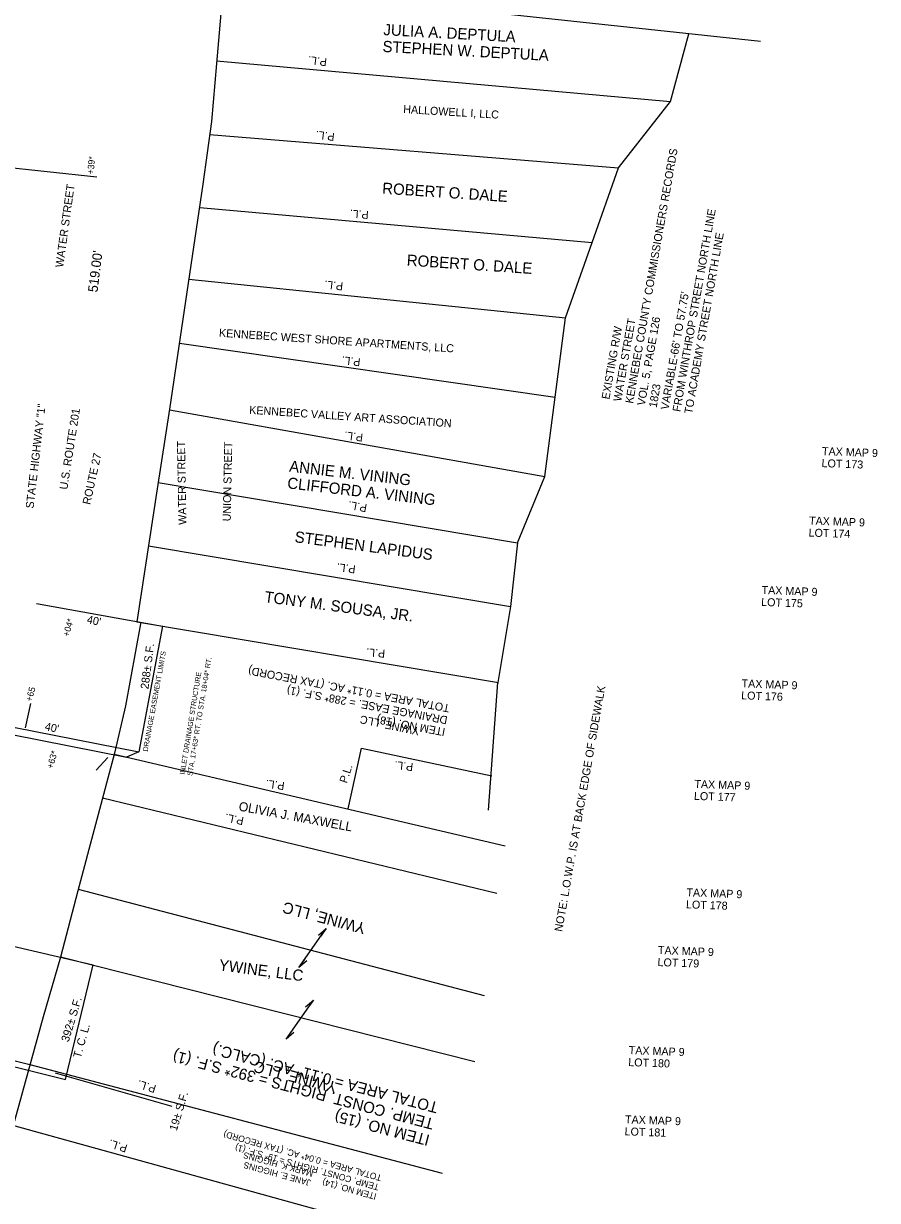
# Model space of a CAD drawing. Extents: x 1133267 to 1139526, y 528613 to 531538.
# Drawn here: x 1137374.5 to 1137641.4, y 529576.6 to 529944.3 of the extents above; entities that cross this region are included whole.
import ezdxf

# ---------------------------------------------------------------- set-up
doc = ezdxf.new("R2010")
doc.units = 0
for name, color, linetype in [('BASELN DIST_NTES', 7, 'Continuous'), ('E_Property_Line', 7, 'Continuous'), ('E_Property_LotLine', 7, 'Continuous'), ('E_ROW_Line', 7, 'Continuous'), ('E_ROW_TieLine', 7, 'Continuous'), ('MISCELLN TEXT', 7, 'Continuous'), ('P_Ease_Perm_Drainage_Line', 7, 'Continuous'), ('P_Ease_Temp_Grading_Line', 7, 'Continuous'), ('P_ROW_Tie_Lines', 7, 'Continuous'), ('PERM DRAINAGE', 7, 'Continuous'), ('PROPERTY LINES', 7, 'Continuous'), ('PROPERTY NOTES', 7, 'Continuous'), ('PRP OWNER NAMES', 7, 'Continuous'), ('PRPTY SETUPS', 7, 'Continuous'), ('ROW REFERENCES', 7, 'Continuous'), ('TEMP RIGHTS', 7, 'Continuous'), ('Temp Rights Text', 7, 'Continuous'), ('TIE DISTANCES', 7, 'Continuous'), ('TIE STATIONS', 7, 'Continuous')]:
    doc.layers.add(name, color=color, linetype=linetype)

msp = doc.modelspace()

# ---------------------------------------------------------------- linework, layer by layer
at = {"layer": 'E_Property_Line'}
for p, q in [((1137436.96, 529956.8), (1137604.82, 529938.75)), ((1137434.86, 529932.6), (1137576.65, 529919.86)), ((1137432.65, 529909.56), (1137560.44, 529899.24)), ((1137429.57, 529886.84), (1137552.18, 529875.83)), ((1137426.16, 529864.41), (1137543.87, 529852.34)), ((1137423.21, 529844.42), (1137540.66, 529827.55)), ((1137420.14, 529823.59), (1137537.43, 529802.76)), ((1137416.58, 529800.87), (1137528.92, 529782.03)), ((1137413.57, 529781.09), (1137526.71, 529762.12)), ((1137411.17, 529757.18), (1137522.93, 529738.43)), ((1137475.92, 529698.93), (1137480.08, 529717.93)), ((1137480.08, 529717.93), (1137520.85, 529709.3)), ((1137402.89, 529716.01), (1137525.03, 529687.45)), ((1137399.24, 529702.37), (1137522.46, 529672.66)), ((1137460.59, 529649.38), (1137469.09, 529661.64)), ((1137456.58, 529626.98), (1137465.08, 529639.24)), ((1137376.52, 529619.09), (1137505.38, 529585.2)), ((1137371.08, 529600.14), (1137505.47, 529563.04))]:
    msp.add_line(p, q, dxfattribs=at)
for points in [[(1137466.67, 529659.52), (1137469.09, 529661.64), (1137469.09, 529661.64), (1137467.31, 529659.07)], [(1137463.01, 529651.5), (1137460.59, 529649.38), (1137460.59, 529649.38), (1137462.37, 529651.95)], [(1137462.65, 529637.12), (1137465.08, 529639.24), (1137465.08, 529639.24), (1137463.3, 529636.67)], [(1137459, 529629.1), (1137456.58, 529626.98), (1137456.58, 529626.98), (1137458.36, 529629.55)]]:
    msp.add_lwpolyline(points, dxfattribs=at)
at = {"layer": 'E_Property_LotLine'}
for p, q in [((1137391.64, 529673.9), (1137518.51, 529640.71)), ((1137386.09, 529652.78), (1137515.53, 529620.05))]:
    msp.add_line(p, q, dxfattribs=at)
at = {"layer": 'E_ROW_Line'}
for points in [[(1137440.95, 530002.64), (1137434.79, 529931.82), (1137433.21, 529913.62), (1137430.53, 529894.11), (1137420.18, 529823.83), (1137416.28, 529798.89), (1137409.93, 529757.4), (1137411.17, 529757.18), (1137411.09, 529756.72), (1137406.41, 529731.14), (1137402.97, 529716.34), (1137391.5, 529673.39), (1137386.04, 529652.6), (1137380.61, 529633.99)], [(1137380.61, 529633.99), (1137373.03, 529606.41), (1137365, 529577.77), (1137365.64, 529577.56), (1137342.79, 529491.93)]]:
    msp.add_lwpolyline(points, dxfattribs=at)
at = {"layer": 'E_ROW_TieLine'}
for p, q in [((1137576.65, 529919.86), (1137582.46, 529941.08)), ((1137560.44, 529899.24), (1137576.65, 529919.86)), ((1137552.18, 529875.83), (1137560.44, 529899.24)), ((1137543.87, 529852.34), (1137552.18, 529875.83)), ((1137540.66, 529827.55), (1137543.87, 529852.34)), ((1137537.43, 529802.76), (1137540.66, 529827.55)), ((1137528.92, 529782.03), (1137537.43, 529802.76)), ((1137528.92, 529782.03), (1137526.71, 529762.12)), ((1137526.71, 529762.12), (1137522.74, 529738.45)), ((1137519.79, 529698.59), (1137522.74, 529738.45))]:
    msp.add_line(p, q, dxfattribs=at)
at = {"layer": 'P_Ease_Perm_Drainage_Line'}
for p, q in [((1137417.95, 529756.04), (1137410.59, 529716.75)), ((1137410.59, 529716.75), (1137406.74, 529715.12))]:
    msp.add_line(p, q, dxfattribs=at)
at = {"layer": 'P_Ease_Temp_Grading_Line'}
msp.add_line((1137387.58, 529614.43), (1137396.26, 529650.21), dxfattribs=at)
at = {"layer": 'P_ROW_Tie_Lines'}
for p, q in [((1137397.4, 529896.31), (1137365.75, 529899.68)), ((1137378.59, 529763.16), (1137417.95, 529756.04)), ((1137376.69, 529731.89), (1137375, 529724.24)), ((1137370.9, 529722.24), (1137406.74, 529715.12)), ((1137371.34, 529724.5), (1137410.59, 529716.75)), ((1137400.91, 529715.02), (1137397.23, 529711.05)), ((1137357.31, 529659.29), (1137396.26, 529650.21)), ((1137349.23, 529625.96), (1137376.52, 529619.09)), ((1137348.78, 529624.18), (1137387.58, 529614.43))]:
    msp.add_line(p, q, dxfattribs=at)
at = {"layer": 'Temp Rights Text'}
msp.add_line((1137421, 529605.95), (1137384.55, 529616.37), dxfattribs=at)

# ---------------------------------------------------------------- texts
at = {"layer": 'BASELN DIST_NTES'}
msp.add_text("519.00'", height=3, rotation=82.7543, dxfattribs=at).set_placement((1137397.6, 529860.18))
at = {"layer": 'MISCELLN TEXT'}
for s, height, rotation, p in [('WATER STREET', 2.5, 82.0323, (1137386.88, 529867.94)), ('STATE HIGHWAY "1"', 2.5, 83.3934, (1137377.65, 529792.69)), ('U.S. ROUTE 201', 2.5, 81.0324, (1137388.18, 529798.54)), ('WATER STREET', 2.5, 91.0683, (1137425.45, 529787.71)), ('UNION STREET', 2.5, 88.8498, (1137439.25, 529788.75)), ('ROUTE 27', 2.5, 77.4889, (1137395.34, 529793.83)), ('NOTE: L.O.W.P. IS AT BACK EDGE OF SIDEWALK', 2.49, 80.0021, (1137542.83, 529660.46))]:
    msp.add_text(s, height=height, rotation=rotation, dxfattribs=at).set_placement(p)
at = {"layer": 'PERM DRAINAGE'}
for s, rotation, p in [('DRAINAGE EASEMENT LIMITS', 79.6091, (1137413.32, 529716.76)), ('STA. 17+63* RT. TO STA. 18+04* RT.', 80.697, (1137427.24, 529709.19)), ('INLET DRAINAGE STRUCTURE', 80.697, (1137424.87, 529709.58))]:
    msp.add_text(s, height=1.59, rotation=rotation, dxfattribs=at).set_placement(p)
at = {"layer": 'PROPERTY LINES'}
for rotation, p in [(172.8375, (1137469.44, 529933.38)), (172.8375, (1137471.84, 529910.04)), (175.9441, (1137482.43, 529885.7)), (173.5705, (1137474.49, 529863.34)), (173.2682, (1137479.91, 529839.66)), (172.8375, (1137480.73, 529816.13)), (169.5777, (1137482, 529794.06)), (172.8375, (1137478.39, 529774.96)), (175.2843, (1137487.6, 529748.64)), (71.8543, (1137475.52, 529706.8)), (173.4169, (1137496.4, 529713.22)), (172.3291, (1137456.21, 529707.28)), (168.3631, (1137443.51, 529696.3)), (162.7266, (1137416.15, 529612.55)), (162.2389, (1137407.18, 529593.94))]:
    msp.add_text('P.L.', height=2.49, rotation=rotation, dxfattribs=at).set_placement(p)
at = {"layer": 'PROPERTY NOTES'}
for s, p in [('TAX MAP 9', (1137624, 529809.47)), ('LOT 173', (1137623.86, 529805.72)), ('TAX MAP 9', (1137619.95, 529787.79)), ('LOT 174', (1137619.81, 529784.04)), ('TAX MAP 9', (1137605.12, 529766.1)), ('LOT 175', (1137604.99, 529762.36)), ('TAX MAP 9', (1137598.87, 529736.93)), ('LOT 176', (1137598.74, 529733.19)), ('TAX MAP 9', (1137584.12, 529705.54)), ('LOT 177', (1137583.98, 529701.79)), ('TAX MAP 9', (1137581.63, 529671.66)), ('LOT 178', (1137581.49, 529667.91)), ('TAX MAP 9', (1137572.73, 529653.62)), ('LOT 179', (1137572.6, 529649.87)), ('TAX MAP 9', (1137563.6, 529622.38)), ('LOT 180', (1137563.46, 529618.63)), ('TAX MAP 9', (1137562.44, 529600.76)), ('LOT 181', (1137562.31, 529597.01))]:
    msp.add_text(s, height=2.5, rotation=357.9281, dxfattribs=at).set_placement(p)
at = {"layer": 'PRP OWNER NAMES'}
for s, height, rotation, p in [('JULIA A. DEPTULA', 3.5, 356.9008, (1137486.9, 529940.65)), ('STEPHEN W. DEPTULA', 3.5, 356.9008, (1137486.62, 529935.41)), ('HALLOWELL I, LLC', 2.5, 356.6076, (1137493.12, 529916.31)), ('ROBERT O. DALE', 3.5, 356.1647, (1137486.52, 529891.13)), ('ROBERT O. DALE', 3.5, 356.1647, (1137494.19, 529868.66)), ('KENNEBEC WEST SHORE APARTMENTS, LLC', 2.5, 356.1647, (1137435.53, 529846.45)), ('KENNEBEC VALLEY ART ASSOCIATION', 2.5, 356.1647, (1137444.98, 529822.38)), ('ANNIE M. VINING', 3.5, 353.4056, (1137457.4, 529804.31)), ('CLIFFORD A. VINING', 3.5, 353.4056, (1137456.8, 529799.09)), ('STEPHEN LAPIDUS', 3.5, 352.5172, (1137459.09, 529782.27)), ('TONY M. SOUSA, JR.', 3.5, 352.5172, (1137449.65, 529763.53)), ('YWINE, LLC', 2.49, 168.0933, (1137498.41, 529724.31)), ('OLIVIA J. MAXWELL', 2.85, 349.4782, (1137441.58, 529698.46)), ('YWINE, LLC', 3.5, 165.1259, (1137481.71, 529663.18)), ('YWINE, LLC', 3.5, 352.5172, (1137435.4, 529648.55)), ('YWINE, LLC', 3.5, 165.3425, (1137472.7, 529613.55)), ('MARK K. HIGGINS', 1.95, 164.6781, (1137465.21, 529585.87)), ('JANE E. HIGGINS', 1.95, 164.6781, (1137464.43, 529583.03))]:
    msp.add_text(s, height=height, rotation=rotation, dxfattribs=at).set_placement(p)
at = {"layer": 'PRPTY SETUPS'}
for s, height, rotation, p in [('TOTAL AREA = 0.11* AC. (TAX RECORD)', 2.5, 169.259, (1137507.86, 529731.51)), ('DRAINAGE EASE. = 288* S.F. (1)', 2.5, 169.259, (1137507.16, 529727.81)), ('ITEM NO. (18)', 2.5, 169.259, (1137506.46, 529724.1)), ('TOTAL AREA = 0.11* AC. (CALC.)', 3.5, 165.2388, (1137504.38, 529607.21)), ('TEMP. CONST. RIGHTS = 392* S.F. (1)', 3.5, 165.2388, (1137503.04, 529602.11)), ('ITEM NO. (15)', 3.5, 165.2388, (1137501.69, 529597.01)), ('TOTAL AREA = 0.04* AC. (TAX RECORD)', 2, 164.2824, (1137486.62, 529584.55)), ('TEMP. CONST. RIGHTS = 19* S.F. (1)', 2, 164.2824, (1137485.8, 529581.65)), ('ITEM NO. (14)', 2, 164.2824, (1137484.98, 529578.74))]:
    msp.add_text(s, height=height, rotation=rotation, dxfattribs=at).set_placement(p)
at = {"layer": 'ROW REFERENCES'}
for s, p in [('KENNEBEC COUNTY COMMISSIONERS RECORDS', (1137564.96, 529825.44)), ('FROM WINTHROP STREET NORTH LINE', (1137579.74, 529822.84)), ('TO ACADEMY STREET NORTH LINE', (1137583.43, 529822.19)), ("VARIABLE-66' TO 57.75'", (1137576.05, 529823.49)), ('WATER STREET', (1137561.27, 529826.08)), ('VOL. 5, PAGE 126', (1137568.66, 529824.79)), ('EXISTING R/W', (1137557.58, 529826.73)), ('1823', (1137572.35, 529824.14))]:
    msp.add_text(s, height=2.5, rotation=80.0459, dxfattribs=at).set_placement(p)
at = {"layer": 'TEMP RIGHTS'}
msp.add_text('T. C. L.', height=2.49, rotation=74.3632, dxfattribs=at).set_placement((1137392.37, 529620.96))
at = {"layer": 'Temp Rights Text'}
for s, rotation, p in [('288± S.F.', 82.6836, (1137413.53, 529736.26)), ('392± S.F.', 73.2515, (1137388.61, 529625.98)), ('19± S.F.', 73.2515, (1137422.4, 529598.2))]:
    msp.add_text(s, height=2.49, rotation=rotation, dxfattribs=at).set_placement(p)
at = {"layer": 'TIE DISTANCES'}
for p in [(1137394.16, 529757.01), (1137381.02, 529723.59)]:
    msp.add_text("40'", height=2.49, rotation=348.2485, dxfattribs=at).set_placement(p)
at = {"layer": 'TIE STATIONS'}
for s, rotation, p in [('+39*', 85.0298, (1137396.41, 529897.09)), ('+04*', 74.2706, (1137388.7, 529752.62)), ('+65', 74.2706, (1137377.06, 529732.34)), ('+63*', 74.2706, (1137383.66, 529711.38))]:
    msp.add_text(s, height=2.01, rotation=rotation, dxfattribs=at).set_placement(p)

doc.saveas('drawing.dxf')
